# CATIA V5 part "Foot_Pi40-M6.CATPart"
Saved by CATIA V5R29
Part number: Foot_Pi40-M6
Source: Unknown
Description: www.shal.co.kr
Bounding box of the stored display mesh (mm): x -20 to 20, y -20 to 20, z 4 to 62
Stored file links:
  C:\가치같이\SmartFactory_BoxErectorConveyor\Boxing(under)\Foot_Pi40-M6.CATPart
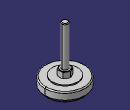
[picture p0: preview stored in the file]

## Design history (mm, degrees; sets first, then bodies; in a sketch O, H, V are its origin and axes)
Body1 (main body)
  Solid1 "PartBody": solid without history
